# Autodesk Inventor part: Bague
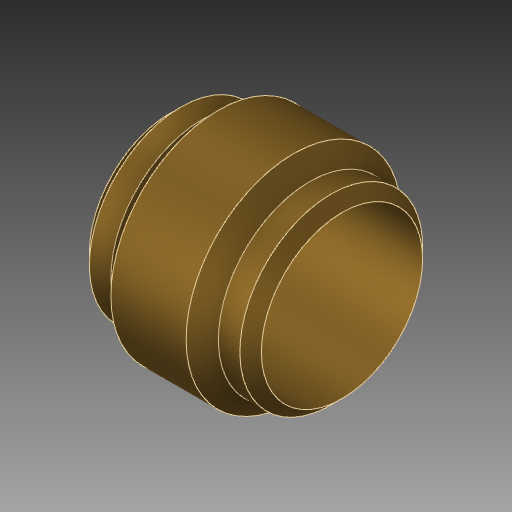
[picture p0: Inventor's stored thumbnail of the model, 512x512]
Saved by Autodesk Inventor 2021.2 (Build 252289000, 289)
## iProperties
Created: 2018-06
Part Number: Bague
Material: Laiton, jaune doux
Document SubType Name: Modeling
Designer: Fabian Perrée
Density: 8.47 g/cm^3
Appearance: Laiton - Satiné
Author: Fabian Perrée
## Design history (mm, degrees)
sketch "Esquisse1"
  geometry: L1 (0, 0)-(8, 0); L2 (0, 3.75)-(8, 3.75); L3 (4, 0)-(4, 10.788); L4 (8, 3.75)-(8, 3.75); L5 (7.5, 4.25)-(6.5, 4.25); L6 (6.5, 4.25)-(6.5, 4.25); L7 (5.75, 5)-(2.25, 5); L8 (1.5, 4.25)-(1.5, 4.25); L9 (1.5, 4.25)-(0.5, 4.25); L10 (0, 3.75)-(0, 3.75); L11 (1.5, 4.25)-(2.25, 5); L12 (5.75, 5)-(6.5, 4.25); L13 (0.5, 4.25)-(0, 3.75); L14 (7.5, 4.25)-(8, 3.75); 4 further points
  constraints: 28 end point, 10 point on line, 5 perpendicular, 2 horizontal, 2 vertical, 2 vertical alignment, 1 midpoint, 1 other
  dimensions: "d0" = 8 distance of L2.start L2.end; "d2" = 7.5 diameter of L2 L1; "d3" = 8.5 diameter of L5 L1; "d4" = 10 diameter of L7 L1; "d6" = 0.75 distance of L8.start point (1.5, 5); "d7" = 0.75 distance of L7.end point (1.5, 5) (= d6); "d8" = 0.75 distance of L7.start point (6.5, 5) (= d6); "d9" = 0.75 distance of L6.end point (6.5, 5) (= d8); "d10" = 0.5 distance of L9.end point (0, 4.25); "d11" = 0.5 distance of L10.start point (0, 4.25) (= d10); "d12" = 0.5 distance of L5.start point (8, 4.25) (= d10); "d13" = 0.5 distance of L4.end point (8, 4.25) (= d12); "d14" = 3.5 distance of L7.start L7.end
revolve "Révolution1" sketch "Esquisse1" stored, may be unused: angle "d5" = 90 deg
node "Solide1"
